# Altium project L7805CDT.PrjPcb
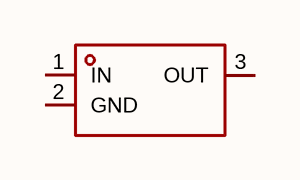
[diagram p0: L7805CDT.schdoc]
1 sheet, 1 parts. Net scope: global (net labels, ports and power ports of the same name join across sheets).

## Sheet L7805CDT.schdoc
size 127 x 101 mm

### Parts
U?  l7805cdt  [TO-252-2_L6.6-W6.1-P4.57-LS9.9-BR-CW]  (value not drawn)

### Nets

Not connected (* = marked no-connect by the designer): U? 1(IN) 2(GND) 3(OUT)

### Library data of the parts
U? = l7805cdt: 输出极性:正极;工作电压:20V;输出电压:5V;输出电流:1A;电源纹波抑制比(PSRR):72dB@(120Hz);输出类型:固定;; Manufacturer: TECH PUBLIC(台舟); AddInBom: yes; ModelId: ce57f84d66384067af8a68020b6de06d; ModelName: TO-252-2L-3P_L6.6-W6.1-H2.3-LS10.1-P4.6; ModelTransform: 259.842,390.52442,0,90,0,0,-39.39,0,0; Output Configuration: 正极; Voltage - Supply: 20V; Output Voltage: 5V; Output Current: 1A; Voltage Dropout: 1V@(300mA); standby current: 8mA; Noise: 42uV; Output Type: 固定; Number of Outputs: 1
